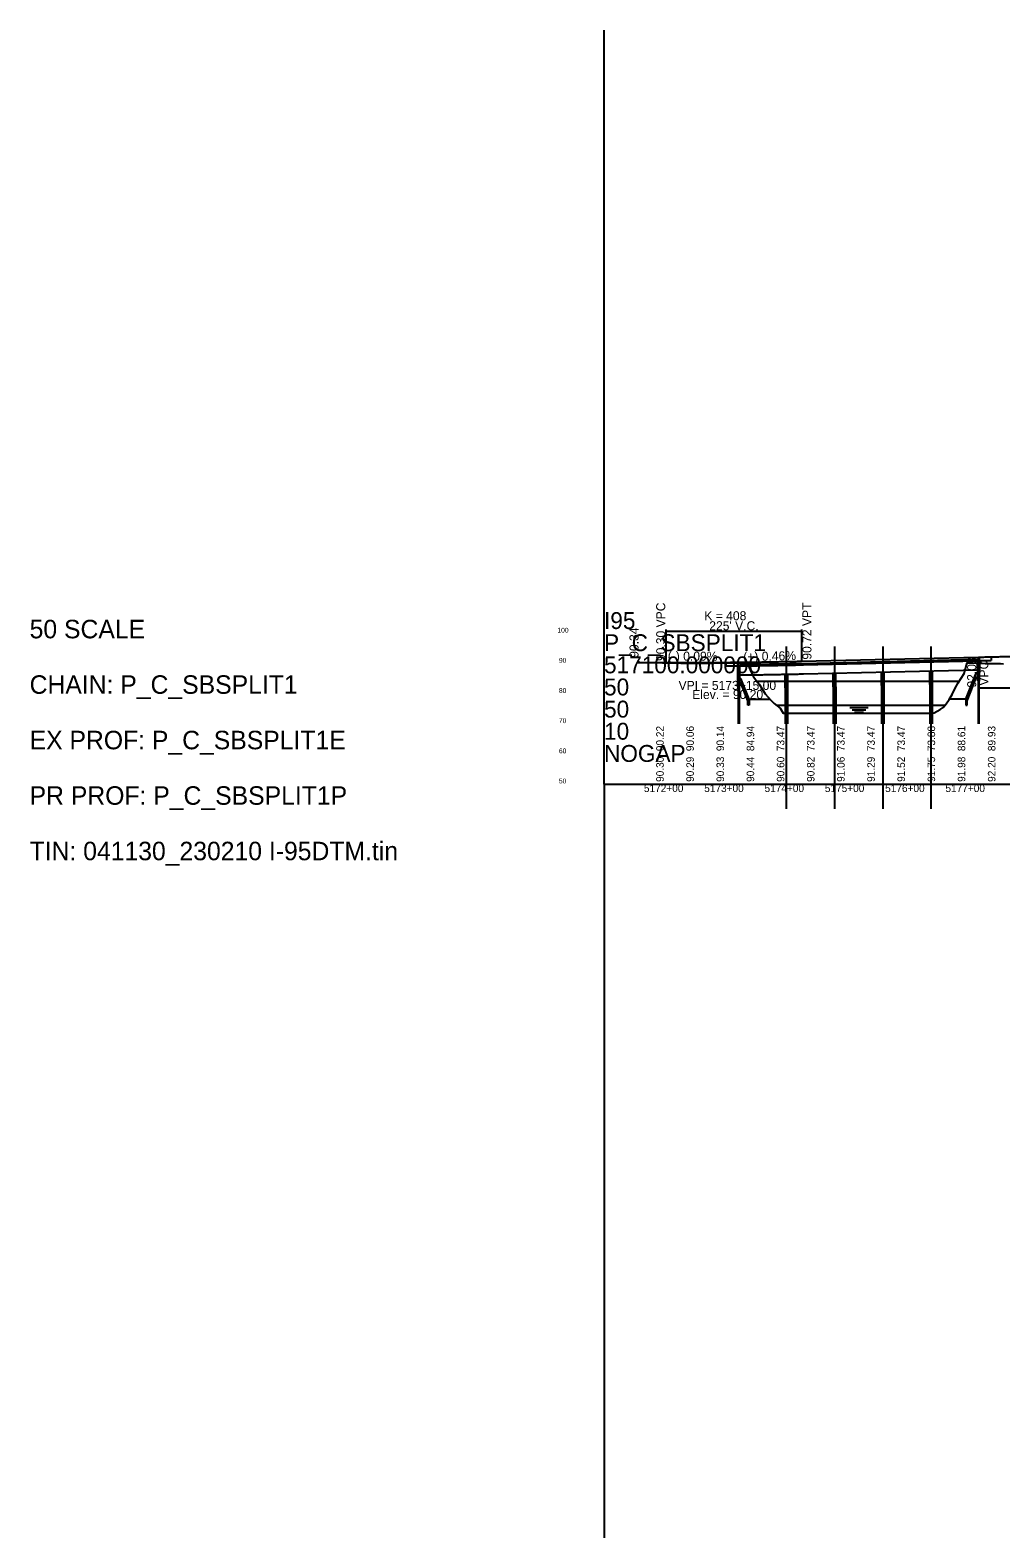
# Model space of a CAD drawing. Extents: x 2121671 to 2169879, y 557274 to 599957.
# Drawn here: x 2145716 to 2147326, y 574937 to 577437 of the extents above; entities that cross this region are included whole.
import ezdxf

# ---------------------------------------------------------------- set-up
doc = ezdxf.new("R2010")
doc.units = 0
for name, color, linetype in [('BR_CENTER LINES', 7, 'Continuous'), ('BR_CONCRETE', 7, 'Continuous'), ('BR_DETAILS', 7, 'Continuous'), ('BR_PRESTRESSED BEAM', 7, 'Continuous'), ('BR_STRUCTURAL STEEL', 7, 'Continuous'), ('RD_DDB_ElevTX', 7, 'Continuous'), ('RD_DDB_GradeTX', 7, 'Continuous'), ('RD_DDB_Profile_Elev', 7, 'Continuous'), ('RD_DDB_Profile_EX', 7, 'Continuous'), ('RD_DDB_Profile_Lbl', 7, 'Continuous'), ('RD_DDB_Profile_PR', 7, 'Continuous'), ('RD_DDB_StaTX', 7, 'Continuous'), ('RD_DDB_StripGrade', 7, 'Continuous'), ('RD_DDB_VCLbl', 7, 'Continuous'), ('RD_GPK_Profile_Cell', 7, 'Continuous'), ('RD_HC_Data_Rel', 7, 'Continuous')]:
    doc.layers.add(name, color=color, linetype=linetype)

msp = doc.modelspace()

# ---------------------------------------------------------------- linework, layer by layer
at = {"layer": 'BR_CENTER LINES'}
for p, q in [((2146970, 576414.7), (2146970, 576145.8)), ((2147050, 576414.7), (2147050, 576266.5)), ((2147050, 576414.7), (2147050, 576145.8)), ((2147130, 576414.7), (2147130, 576264.4)), ((2147130, 576414.7), (2147130, 576145.8)), ((2147210, 576414.7), (2147210, 576289.1)), ((2147210, 576414.7), (2147210, 576145.8))]:
    msp.add_line(p, q, dxfattribs=at)
at = {"layer": 'BR_CONCRETE'}
for p, q in [((2146870, 576388.5), (2146870, 576382.7)), ((2146889.3, 576382.8), (2146889.3, 576366.9)), ((2146890, 576388.7), (2146890, 576382.8)), ((2146892.8, 576366.9), (2146892.8, 576385.2)), ((2146998.8, 576386.9), (2147287.2, 576393.6)), ((2147287.2, 576375.4), (2147287.2, 576393.6)), ((2147290, 576397.2), (2147290, 576391.4)), ((2147290, 576391.4), (2147292.2, 576391.4)), ((2147290.7, 576391.4), (2147290.7, 576375.4)), ((2147310, 576397.7), (2147310, 576391.8)), ((2147208, 576351.8), (2147208, 576286.7)), ((2147212, 576351.8), (2147212, 576286.7)), ((2146968, 576346.3), (2146968, 576286.7)), ((2146972, 576346.3), (2146972, 576286.7)), ((2147048, 576348.1), (2147048, 576286.7)), ((2147052, 576348.1), (2147052, 576286.7)), ((2147128, 576349.9), (2147128, 576286.7)), ((2147132, 576349.9), (2147132, 576286.7))]:
    msp.add_line(p, q, dxfattribs=at)
for points in [[(2147287.2, 576357.9), (2147290.7, 576357.9), (2147290.7, 576375.4), (2147287.2, 576375.4)], [(2146889.3, 576349.4), (2146892.8, 576349.4), (2146892.8, 576366.9), (2146889.3, 576366.9)], [(2146967.5, 576346.3), (2146972.5, 576346.3), (2146972.5, 576366.3), (2146967.5, 576366.3)], [(2147047.5, 576348.1), (2147052.5, 576348.1), (2147052.5, 576368.1), (2147047.5, 576368.1)], [(2147127.5, 576349.9), (2147132.5, 576349.9), (2147132.5, 576369.9), (2147127.5, 576369.9)], [(2147207.5, 576351.8), (2147212.5, 576351.8), (2147212.5, 576371.8), (2147207.5, 576371.8)]]:
    msp.add_lwpolyline(points, close=True, dxfattribs=at)
for points in [[(2146870, 576382.7), (2146872.8, 576382.7), (2146877.3, 576382.7), (2146881.8, 576382.8), (2146886.3, 576382.8), (2146890, 576382.8)], [(2146892.8, 576385.2), (2146895.3, 576385.2), (2146899.8, 576385.2), (2146904.3, 576385.3), (2146908.8, 576385.3), (2146913.3, 576385.4), (2146917.8, 576385.5), (2146922.3, 576385.5), (2146926.8, 576385.6), (2146931.3, 576385.6), (2146935.8, 576385.7), (2146940.3, 576385.8), (2146944.8, 576385.9), (2146949.3, 576385.9), (2146953.8, 576386), (2146958.3, 576386.1), (2146962.8, 576386.2), (2146967.3, 576386.3), (2146971.8, 576386.3), (2146976.3, 576386.4), (2146980.8, 576386.5), (2146985.3, 576386.6), (2146989.8, 576386.7), (2146994.3, 576386.8), (2146998.8, 576386.9)], [(2147292.2, 576391.4), (2147301.2, 576391.6), (2147310, 576391.8)]]:
    msp.add_spline(points, degree=3, dxfattribs=at)
at = {"layer": 'BR_DETAILS'}
for p, q in [((2146892.8, 576361.9), (2146894.8, 576361.9)), ((2146892.8, 576354.4), (2146894.8, 576354.4)), ((2146908.6, 576327.5), (2146894.8, 576361.9)), ((2146906.6, 576325), (2146894.8, 576354.4)), ((2147268, 576327.5), (2147285.2, 576370.4)), ((2147270, 576325), (2147285.2, 576362.9)), ((2147287.2, 576370.4), (2147285.2, 576370.4)), ((2147287.2, 576362.9), (2147285.2, 576362.9)), ((2146908.6, 576327.5), (2146908.6, 576317.5)), ((2146908.6, 576327.5), (2146943.1, 576327.5)), ((2147268, 576327.5), (2147240.4, 576327.5)), ((2147268, 576327.5), (2147268, 576317.5)), ((2146906.6, 576317.5), (2146906.6, 576325)), ((2146908.6, 576317.5), (2146906.6, 576317.5)), ((2147268, 576317.5), (2147270, 576317.5)), ((2147270, 576317.5), (2147270, 576325))]:
    msp.add_line(p, q, dxfattribs=at)
for points in [[(2146968.5, 576368.8), (2146969.5, 576368.8), (2146969.5, 576366.3), (2146968.5, 576366.3)], [(2146970.5, 576368.8), (2146971.5, 576368.8), (2146971.5, 576366.3), (2146970.5, 576366.3)], [(2147048.5, 576370.6), (2147049.5, 576370.6), (2147049.5, 576368.1), (2147048.5, 576368.1)], [(2147050.5, 576370.6), (2147051.5, 576370.6), (2147051.5, 576368.1), (2147050.5, 576368.1)], [(2147128.5, 576372.4), (2147129.5, 576372.4), (2147129.5, 576369.9), (2147128.5, 576369.9)], [(2147130.5, 576372.4), (2147131.5, 576372.4), (2147131.5, 576369.9), (2147130.5, 576369.9)], [(2147208.5, 576374.3), (2147209.5, 576374.3), (2147209.5, 576371.8), (2147208.5, 576371.8)], [(2147210.5, 576374.3), (2147211.5, 576374.3), (2147211.5, 576371.8), (2147210.5, 576371.8)]]:
    msp.add_lwpolyline(points, close=True, dxfattribs=at)
at = {"layer": 'BR_PRESTRESSED BEAM'}
for p, q in [((2146998.8, 576384.4), (2147287.2, 576391.1)), ((2146998.8, 576369.4), (2147287.2, 576376.1))]:
    msp.add_line(p, q, dxfattribs=at)
for points in [[(2146892.8, 576382.7), (2146895.3, 576382.7), (2146899.8, 576382.7), (2146904.3, 576382.8), (2146908.8, 576382.8), (2146913.3, 576382.9), (2146917.8, 576383), (2146922.3, 576383), (2146926.8, 576383.1), (2146931.3, 576383.1), (2146935.8, 576383.2), (2146940.3, 576383.3), (2146944.8, 576383.4), (2146949.3, 576383.4), (2146953.8, 576383.5), (2146958.3, 576383.6), (2146962.8, 576383.7), (2146967.3, 576383.8), (2146971.8, 576383.8), (2146976.3, 576383.9), (2146980.8, 576384), (2146985.3, 576384.1), (2146989.8, 576384.2), (2146994.3, 576384.3), (2146998.8, 576384.4)], [(2146892.8, 576367.7), (2146895.3, 576367.7), (2146899.8, 576367.7), (2146904.3, 576367.8), (2146908.8, 576367.8), (2146913.3, 576367.9), (2146917.8, 576368), (2146922.3, 576368), (2146926.8, 576368.1), (2146931.3, 576368.1), (2146935.8, 576368.2), (2146940.3, 576368.3), (2146944.8, 576368.4), (2146949.3, 576368.4), (2146953.8, 576368.5), (2146958.3, 576368.6), (2146962.8, 576368.7), (2146967.3, 576368.8), (2146971.8, 576368.8), (2146976.3, 576368.9), (2146980.8, 576369), (2146985.3, 576369.1), (2146989.8, 576369.2), (2146994.3, 576369.3), (2146998.8, 576369.4)]]:
    msp.add_spline(points, degree=3, dxfattribs=at)
at = {"layer": 'BR_STRUCTURAL STEEL'}
for p, q in [((2147288.3, 576357.9), (2147288.3, 576286.7)), ((2147289.5, 576357.9), (2147289.5, 576286.7)), ((2146890.5, 576349.4), (2146890.5, 576286.7)), ((2146891.7, 576349.4), (2146891.7, 576286.7))]:
    msp.add_line(p, q, dxfattribs=at)
at = {"layer": 'RD_DDB_GradeTX'}
msp.add_line((2146820.9, 576388.1), (2146881.9, 576387.8), dxfattribs=at)
msp.add_circle((2146725.1, 576388.5), 1, dxfattribs=at)
at = {"layer": 'RD_DDB_Profile_Elev'}
for p, q in [((2146920.9, 576357.4), (2147257, 576357.4)), ((2146954.1, 576317.4), (2147233.2, 576317.4)), ((2147075.7, 576313.7), (2147105.7, 576313.7)), ((2147079.5, 576309.9), (2147102, 576309.9)), ((2147083.2, 576306.2), (2147098.2, 576306.2))]:
    msp.add_line(p, q, dxfattribs=at)
at = {"layer": 'RD_DDB_Profile_EX'}
for points in [[(2146725.1, 576388.5), (2146730.1, 576388.5), (2146735.1, 576388.4), (2146740.1, 576388.4), (2146745.1, 576388.4), (2146750.1, 576388.3), (2146755.1, 576388.2), (2146760.1, 576388.1), (2146765.1, 576388), (2146770.1, 576387.9), (2146775.1, 576387.8), (2146780.1, 576387.7), (2146785.1, 576387.6), (2146790.1, 576387.5), (2146795.1, 576387.4), (2146800.1, 576387.2), (2146805.1, 576387.1), (2146810.1, 576387.1), (2146815.1, 576387.1), (2146820.1, 576387.2), (2146825.1, 576387.2), (2146830.1, 576387.3), (2146835.1, 576387.4), (2146840.1, 576387.4), (2146845.1, 576387.4), (2146850.1, 576387.4), (2146855.1, 576387.5), (2146860.1, 576387.5), (2146865.1, 576387.5), (2146870.1, 576387.5), (2146875.1, 576387.6), (2146880.1, 576387.6), (2146885.1, 576387.7), (2146890.1, 576387.8), (2146895.1, 576387.9), (2146900.1, 576387.9), (2146905.1, 576388), (2146910.1, 576376.3), (2146915.1, 576365.5), (2146920.1, 576358.4), (2146925.1, 576352.4), (2146930.1, 576344.5), (2146935.1, 576336.5), (2146940.1, 576330.8), (2146945.1, 576325.2), (2146950.1, 576320.5), (2146955.1, 576316.6), (2146960.1, 576312.4), (2146965.1, 576304.2), (2146970.1, 576304.2), (2146975.1, 576304.2), (2146980.1, 576304.2), (2146985.1, 576304.2), (2146990.1, 576304.2), (2146995.1, 576304.2), (2147000.1, 576304.2), (2147005.1, 576304.2), (2147010.1, 576304.2), (2147015.1, 576304.2), (2147020.1, 576304.2), (2147025.1, 576304.2), (2147030.1, 576304.2), (2147035.1, 576304.2), (2147040.1, 576304.2), (2147045.1, 576304.2), (2147050.1, 576304.2), (2147055.1, 576304.2), (2147060.1, 576304.2), (2147065.1, 576304.2), (2147070.1, 576304.2), (2147075.1, 576304.2), (2147080.1, 576304.2), (2147085.1, 576304.2), (2147090.1, 576304.2), (2147095.1, 576304.2), (2147100.1, 576304.2), (2147105.1, 576304.2), (2147110.1, 576304.2), (2147115.1, 576304.2), (2147120.1, 576304.2), (2147125.1, 576304.2), (2147130.1, 576304.2), (2147135.1, 576304.2), (2147140.1, 576304.2), (2147145.1, 576304.2), (2147150.1, 576304.2), (2147155.1, 576304.2), (2147160.1, 576304.2), (2147165.1, 576304.2), (2147170.1, 576304.2), (2147175.1, 576304.2), (2147180.1, 576304.2), (2147185.1, 576304.2), (2147190.1, 576304.2), (2147195.1, 576304.2), (2147200.1, 576304.2), (2147205.1, 576304.2), (2147210.1, 576304.2), (2147215.1, 576304.7), (2147220.1, 576307.5), (2147225.1, 576310.3)], [(2147225.1, 576310.3), (2147230.1, 576313.6), (2147235.1, 576319.8), (2147240.1, 576327), (2147245.1, 576335.4), (2147250.1, 576345.5), (2147255.1, 576354.4), (2147260.1, 576362.5), (2147265.1, 576369.8), (2147270.1, 576387.8), (2147275.1, 576387.7), (2147280.1, 576387.5), (2147285.1, 576387.3), (2147290.1, 576387.1), (2147295.1, 576387), (2147300.1, 576386.8), (2147305.1, 576386.6), (2147310.1, 576386.5), (2147315.1, 576386.5), (2147320.1, 576386.4), (2147325.1, 576386.4), (2147330.1, 576386.3)]]:
    msp.add_lwpolyline(points, dxfattribs=at)
at = {"layer": 'RD_DDB_Profile_PR'}
for p, q in [((2146725.1, 576388.5), (2146770.4, 576388.3)), ((2146995.4, 576390.4), (2147288.8, 576397.2))]:
    msp.add_line(p, q, dxfattribs=at)
for points in [[(2146770.4, 576388.3), (2146774.9, 576388.3), (2146779.4, 576388.3), (2146783.9, 576388.3), (2146788.4, 576388.3), (2146792.9, 576388.3), (2146797.4, 576388.3), (2146801.9, 576388.3), (2146806.4, 576388.2), (2146810.9, 576388.3), (2146815.4, 576388.3), (2146819.9, 576388.3), (2146824.4, 576388.3), (2146828.9, 576388.3), (2146833.4, 576388.3), (2146837.9, 576388.3), (2146842.4, 576388.3), (2146846.9, 576388.3), (2146851.4, 576388.4), (2146855.9, 576388.4), (2146860.4, 576388.4), (2146864.9, 576388.5), (2146869.4, 576388.5), (2146873.9, 576388.5), (2146878.4, 576388.6), (2146882.9, 576388.6), (2146887.4, 576388.6), (2146891.9, 576388.7), (2146896.4, 576388.7), (2146900.9, 576388.8), (2146905.4, 576388.8), (2146909.9, 576388.9), (2146914.4, 576389), (2146918.9, 576389), (2146923.4, 576389.1), (2146927.9, 576389.1), (2146932.4, 576389.2), (2146936.9, 576389.3), (2146941.4, 576389.4), (2146945.9, 576389.4), (2146950.4, 576389.5), (2146954.9, 576389.6), (2146959.4, 576389.7), (2146963.9, 576389.8), (2146968.4, 576389.9), (2146972.9, 576389.9), (2146977.4, 576390), (2146981.9, 576390.1), (2146986.4, 576390.2), (2146990.9, 576390.3), (2146995.4, 576390.4)], [(2147288.8, 576397.2), (2147297.8, 576397.4), (2147306.8, 576397.6), (2147315.8, 576397.8), (2147324.8, 576398), (2147333.8, 576398.2), (2147342.8, 576398.3), (2147351.8, 576398.5), (2147360.8, 576398.6), (2147369.8, 576398.7), (2147378.8, 576398.9), (2147387.8, 576399), (2147396.8, 576399.1), (2147405.8, 576399.2), (2147414.8, 576399.3), (2147423.8, 576399.3), (2147432.8, 576399.4), (2147441.8, 576399.5), (2147450.8, 576399.5), (2147459.8, 576399.6), (2147468.8, 576399.6), (2147477.8, 576399.6), (2147486.8, 576399.6), (2147495.8, 576399.6), (2147504.8, 576399.6), (2147513.8, 576399.6), (2147522.8, 576399.6), (2147531.8, 576399.6), (2147540.8, 576399.5), (2147549.8, 576399.5), (2147558.8, 576399.4), (2147567.8, 576399.4), (2147576.8, 576399.3), (2147585.8, 576399.2), (2147594.8, 576399.1), (2147603.8, 576399), (2147612.8, 576398.9), (2147621.8, 576398.8), (2147630.8, 576398.6), (2147639.8, 576398.5), (2147648.8, 576398.4), (2147657.8, 576398.2), (2147666.8, 576398), (2147675.8, 576397.9), (2147684.8, 576397.7), (2147693.8, 576397.5), (2147702.8, 576397.3), (2147711.8, 576397.1), (2147720.8, 576396.9), (2147729.8, 576396.6), (2147738.8, 576396.4)]]:
    msp.add_spline(points, degree=3, dxfattribs=at)
at = {"layer": 'RD_DDB_VCLbl'}
for p, q in [((2146770.4, 576442.9), (2146770.4, 576388.3)), ((2146770.4, 576440.4), (2146995.4, 576440.4)), ((2146995.4, 576442.9), (2146995.4, 576390.4)), ((2147288.8, 576343.9), (2147288.8, 576397.2)), ((2147288.8, 576346.4), (2147738.8, 576346.4))]:
    msp.add_line(p, q, dxfattribs=at)
at = {"layer": 'RD_GPK_Profile_Cell'}
for q in [(2146667.9, 577436.8), (2151167.9, 576186.8), (2146667.9, 574936.8)]:
    msp.add_line((2146667.9, 576186.8), q, dxfattribs=at)

# ---------------------------------------------------------------- texts
at = {"layer": 'RD_DDB_ElevTX'}
for s, p in [('100', (2146590.6, 576437.8)), ('90', (2146593.1, 576387.8)), ('80', (2146593.1, 576337.8)), ('70', (2146593.1, 576287.8)), ('60', (2146593.1, 576237.8)), ('50', (2146593.1, 576187.8))]:
    msp.add_text(s, height=8, dxfattribs=at).set_placement(p)
at = {"layer": 'RD_DDB_GradeTX'}
for s, rotation, p in [('(-) 0.09%', 359.7447, (2146773.5, 576391.5)), ('(+) 0.46%', 1.3258, (2146898.9, 576390.4))]:
    msp.add_text(s, height=15, rotation=rotation, dxfattribs=at).set_placement(p)
at = {"layer": 'RD_DDB_Profile_Lbl'}
msp.add_text('90.34', height=15, rotation=90, dxfattribs=at).set_placement((2146725.1, 576396.1))
for s, p in [('VPI = 5173+15.00', (2146791.5, 576342.8)), ('Elev. = 90.20', (2146814.1, 576327.8))]:
    msp.add_text(s, height=15, dxfattribs=at).set_placement(p)
at = {"layer": 'RD_DDB_StaTX'}
for s, p in [('5172+00', (2146734, 576173.5)), ('5173+00', (2146834, 576173.5)), ('5174+00', (2146934, 576173.5)), ('5175+00', (2147034, 576173.5)), ('5176+00', (2147134, 576173.5)), ('5177+00', (2147234, 576173.5))]:
    msp.add_text(s, height=12.5, dxfattribs=at).set_placement(p)
at = {"layer": 'RD_DDB_StripGrade'}
for s, height, p in [('90.30 VPC', 15, (2146769.4, 576390.7)), ('90.72 VPT', 15, (2147011.8, 576393)), ('92.08 ', 15, (2147285, 576346.7)), ('VPC', 15, (2147305.2, 576350)), ('90.22', 12.5, (2146766.9, 576241.3)), ('90.06', 12.5, (2146816.9, 576241.3)), ('90.14', 12.5, (2146866.9, 576241.3)), ('84.94', 12.5, (2146916.9, 576241.3)), ('73.47', 12.5, (2146966.9, 576241.3)), ('73.47', 12.5, (2147016.9, 576241.3)), ('73.47', 12.5, (2147066.9, 576241.3)), ('73.47', 12.5, (2147116.9, 576241.3)), ('73.47', 12.5, (2147166.9, 576241.3)), ('73.88', 12.5, (2147216.9, 576241.3)), ('88.61', 12.5, (2147266.9, 576241.3)), ('89.93', 12.5, (2147316.9, 576241.3)), ('90.30', 12.5, (2146766.9, 576190.3)), ('90.29', 12.5, (2146816.9, 576190.3)), ('90.33', 12.5, (2146866.9, 576190.3)), ('90.44', 12.5, (2146916.9, 576190.3)), ('90.60', 12.5, (2146966.9, 576190.3)), ('90.82', 12.5, (2147016.9, 576190.3)), ('91.06', 12.5, (2147066.9, 576190.3)), ('91.29', 12.5, (2147116.9, 576190.3)), ('91.52', 12.5, (2147166.9, 576190.3)), ('91.75', 12.5, (2147216.9, 576190.3)), ('91.98', 12.5, (2147266.9, 576190.3)), ('92.20', 12.5, (2147316.9, 576190.3))]:
    msp.add_text(s, height=height, rotation=90, dxfattribs=at).set_placement(p)
at = {"layer": 'RD_DDB_VCLbl'}
for s, p in [('K = 408', (2146834.2, 576458.3)), ("225' V.C.", (2146842.4, 576441.7))]:
    msp.add_text(s, height=15, dxfattribs=at).set_placement(p)
at = {"layer": 'RD_GPK_Profile_Cell'}
for s, p in [('I95', (2146667.9, 576443.8)), ('P_C_SBSPLIT1', (2146667.9, 576407.1)), ('517100.000000', (2146667.9, 576370.4)), ('50', (2146667.9, 576333.7)), ('50', (2146667.9, 576297)), ('10', (2146667.9, 576260.3)), ('NOGAP', (2146667.9, 576223.5))]:
    msp.add_text(s, height=28, dxfattribs=at).set_placement(p)
at = {"layer": 'RD_HC_Data_Rel'}
for s, height, p in [('50 SCALE', 30.67, (2145715.4, 576428.4)), ('CHAIN: P_C_SBSPLIT1', 30.668, (2145715.4, 576336.4)), ('EX PROF: P_C_SBSPLIT1E', 30.668, (2145715.4, 576244.4)), ('PR PROF: P_C_SBSPLIT1P', 30.668, (2145715.4, 576152.4)), ('TIN: 041130_230210 I-95DTM.tin', 30.668, (2145715.4, 576060.4))]:
    msp.add_text(s, height=height, rotation=360, dxfattribs=at).set_placement(p)

doc.saveas('drawing.dxf')
